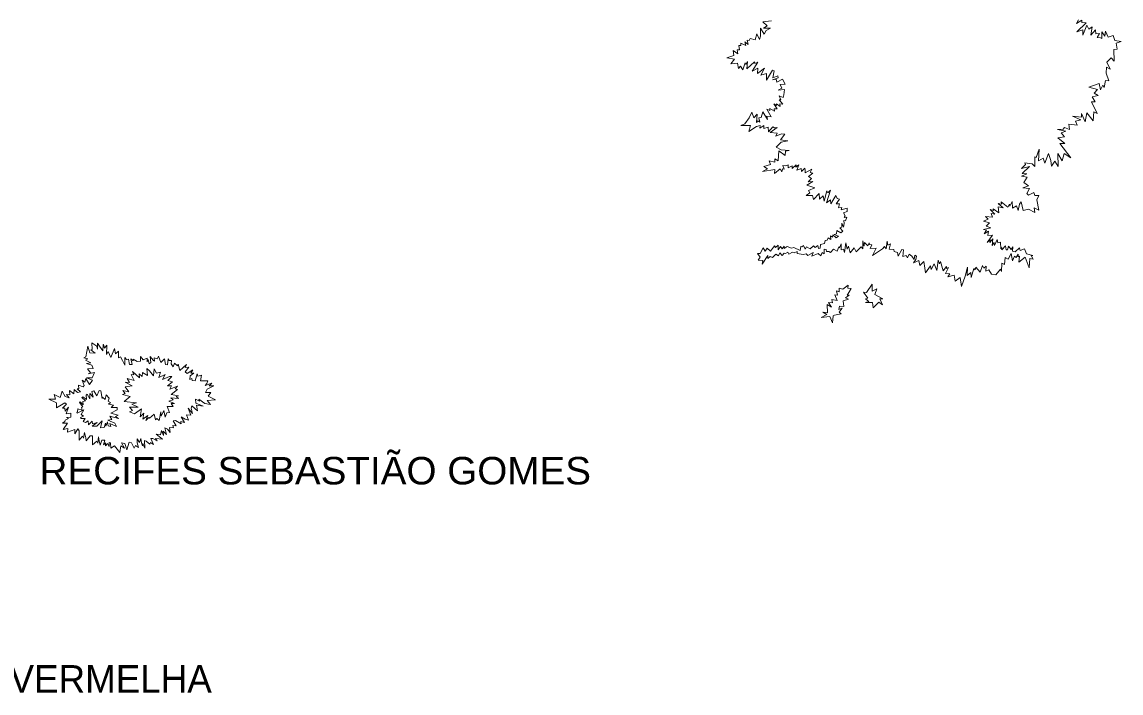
# Model space of a CAD drawing. Extents: x 47169 to 972804, y 7447977 to 9608469.
# Drawn here: x 483748 to 509726, y 8012871 to 8028731 of the extents above; entities that cross this region are included whole.
import ezdxf

# ---------------------------------------------------------------- set-up
doc = ezdxf.new("R2010")
doc.units = 0
doc.header["$LTSCALE"] = 270
doc.layers.add('1', color=7, linetype='Continuous', lineweight=13)
doc.layers.add('3', color=7, linetype='Continuous')

msp = doc.modelspace()

# ---------------------------------------------------------------- linework, layer by layer
at = {"layer": '1'}
for points in [[(500832.5, 8026326.6), (500934.2, 8026466), (501003.1, 8026598.7), (501048.6, 8026463.8), (501127, 8026550), (501106.9, 8026354.2), (501139.8, 8026397.4), (501188.5, 8026366.4), (501163.1, 8026463.8), (501219.2, 8026473.7), (501257.4, 8026605.4), (501369.7, 8026422.8), (501351.7, 8026506.9), (501455.5, 8026485.9), (501351.7, 8026669.5), (501428, 8026638.5), (501428, 8026689.4), (501539.2, 8026623), (501529.7, 8026681.7), (501598.6, 8026679.5), (501519.1, 8026796.7), (501580.6, 8026755.8), (501582.7, 8026796.7), (501671.7, 8026732.6), (501659, 8026796.7), (501733.2, 8026789), (501642, 8026887.5), (501682.3, 8026887.5), (501642, 8026984.8), (501738.5, 8026946.1), (501756.5, 8027010.2), (501771.3, 8027134.2), (501624, 8027118.7), (501709.9, 8027167.4), (501669.6, 8027255.9), (501784, 8027259.2), (501722.6, 8027375.4), (501593.3, 8027306.8), (501573.2, 8027378.7), (501489.5, 8027363.2), (501624.1, 8027414.1), (501611.4, 8027455), (501493.7, 8027408.6), (501529.8, 8027576.7), (501489.5, 8027594.4), (501344.3, 8027357.7), (501349.6, 8027510.4), (501208.7, 8027475), (501303, 8027637.6), (501130.3, 8027510.4), (501140.9, 8027637.6), (501008.4, 8027566.8), (501137.7, 8027784.8), (501072, 8027747.1), (501059.3, 8027792.5), (500881.3, 8027619.9), (500899.3, 8027800.2), (500861.2, 8027726.1), (500843.1, 8027764.9), (500789.1, 8027596.7), (500730.8, 8027688.5), (500683.1, 8027627.7), (500657.7, 8027757.1), (500507.2, 8027743.8), (500588.8, 8027851.2), (500407.6, 8027884.4), (500570.8, 8027935.2), (500560.2, 8028056.9), (500672.5, 8027980.6), (500652.4, 8028074.6), (500710.7, 8028069.1), (500692.7, 8028176.4), (500738.2, 8028176.4), (500739.3, 8028227.3), (500861.2, 8028178.6), (500837.9, 8028260.5), (500914.2, 8028199.7), (500888.7, 8028303.6), (500937.5, 8028295.9), (500962.9, 8028339), (501079.5, 8028311.4), (501117.6, 8028453), (501181.2, 8028315.8), (501201.3, 8028397.7), (501204.5, 8028582.4), (501293.5, 8028440.8), (501342.3, 8028527.1), (501438.7, 8028582.4), (501273.4, 8028582.4), (501364.5, 8028638.8), (501257.5, 8028730.7), (501464.2, 8028760.5)], [(508722, 8028784.1), (508671.1, 8028694.5), (508801.5, 8028770.8), (508803.5, 8028717.7), (508905.3, 8028712.1), (508681.6, 8028494.3), (508821.5, 8028547.3), (508821.4, 8028417.9), (508920.1, 8028654.6), (508963.5, 8028562.7), (509045.1, 8028613.6), (509012.2, 8028422.2), (509123.5, 8028545), (509131.9, 8028453.1), (509215.7, 8028455.3), (509161.6, 8028361.3), (509241, 8028353.5), (509276, 8028341.3), (509276.1, 8028496.2), (509342.8, 8028397.7), (509355.6, 8028513.9), (509424.4, 8028372.2), (509543.1, 8028412), (509576.9, 8028290.3), (509726.3, 8028272.5), (509615, 8028227.2), (509637.2, 8028086.7), (509555.6, 8028082.3), (509564, 8027807.9), (509497.2, 8027884.3), (509388.1, 8027782.6), (509471.7, 8027612.1), (509380.6, 8027663.1), (509372, 8027520.4), (509440.8, 8027340), (509357.1, 8027350), (509324.2, 8027182.9), (509293.5, 8027236), (509240.5, 8027126.6), (509206.6, 8027273.7), (508962.9, 8027193.1), (509173.7, 8027132.1), (509095.3, 8027050.3), (509184.2, 8026991.6), (509044.4, 8026961.8), (509112.1, 8026844.5), (509026.3, 8026842.3), (509160.7, 8026570.1), (509086.6, 8026605.5), (509064.2, 8026397.5), (508917, 8026580.2), (508875.6, 8026370), (508794.1, 8026564.7), (508792, 8026484), (508577.9, 8026501.8), (508773.9, 8026417.6), (508648.9, 8026384.5), (508690.2, 8026290.4), (508492, 8026315.9)], [(503123.9, 8023975.3), (503164.2, 8023881.3), (503182.2, 8023967.6), (503174.8, 8024038.4), (503209.8, 8024028.4), (503242.6, 8024114.7), (503182.2, 8024112.5), (503204.5, 8024150.1), (503169.5, 8024216.5), (503253.2, 8024255.2), (503251.1, 8024330.5), (503113.4, 8024287.3), (503126.1, 8024343.8), (503044.5, 8024338.2), (503075.3, 8024432.3), (502996.9, 8024435.6), (503070, 8024544), (503013.9, 8024555.1), (502986.3, 8024628.1), (502869.7, 8024432.3), (502857, 8024524.1), (502764.9, 8024453.3), (502857.1, 8024753.1), (502795.6, 8024696.7), (502775.5, 8024743.2), (502708.7, 8024498.7), (502686.5, 8024618.2), (502602.8, 8024544.1), (502594.3, 8024676.8), (502459.8, 8024537.5), (502434.3, 8024633.7), (502283.9, 8024633.7), (502370.8, 8024692.4), (502340, 8024747.7), (502490.5, 8024808.5), (502301.9, 8024877.1), (502439.7, 8024959), (502330.5, 8024951.2), (502406.8, 8025033.1), (502340.1, 8025078.5), (502445, 8025154.8), (502381.4, 8025176.9), (502421.7, 8025251.1), (502263.8, 8025167), (502263.8, 8025227.9), (502249, 8025276.5), (502170.6, 8025195.8), (502162.1, 8025264.4), (502065.7, 8025227.9), (502114.5, 8025352.9), (502043.5, 8025302), (502047.7, 8025355.1), (501953.4, 8025271), (501951.3, 8025333), (501854.9, 8025282.1), (501854.9, 8025355.1), (501804, 8025327.5), (501733, 8025335.2), (501765.9, 8025253.3), (501727.7, 8025261.1), (501711.8, 8025188.1), (501669.5, 8025256.7), (501533.8, 8025147.2), (501542.3, 8025246.7), (501254.1, 8025195.9), (501373.9, 8025258.9), (501282.7, 8025317.5), (501442.7, 8025365.1), (501412, 8025449.2), (501544.4, 8025421.5), (501542.3, 8025497.9), (501620.7, 8025449.2), (501640.9, 8025685.9), (501791.3, 8025574.2), (501793.4, 8025678.2), (501885.6, 8025693.7), (501691.7, 8025709.2), (501572, 8025768.9), (501689.6, 8025893.9), (501852.8, 8025924.9), (501674.8, 8025947), (501776.5, 8026082), (501704.5, 8026084.2), (501564.6, 8026034.5), (501600.7, 8026103), (501435.4, 8026115.2), (501595.4, 8026240.2), (501539.2, 8026229.2), (501493.6, 8026254.6), (501397.2, 8026135.2), (501384.5, 8026244.7), (501282.8, 8026211.5), (501284.9, 8026283.4), (501190.6, 8026222.6), (501199.1, 8026287.8), (501110.1, 8026258), (500928.9, 8026138.5), (500964.9, 8026285.6), (500748.8, 8026287.9), (500741.4, 8026287.9), (500832.5, 8026326.6)], [(508492, 8026315.9), (508512.1, 8026186.5), (508390.3, 8026239.6), (508359.5, 8026199.8), (508221.8, 8026192.1), (508419.9, 8026153.3), (508312.9, 8026113.5), (508389.1, 8026016.2), (508229.1, 8025994.1), (508401.8, 8025856.8), (508277.8, 8025861.3), (508539.4, 8025523.7), (508379.4, 8025622.3), (508338, 8025451.9), (508236.4, 8025625.7), (508243.7, 8025314.8), (508163.2, 8025437.6), (508086.9, 8025325.9), (508068.9, 8025457.6), (508010.7, 8025620.2), (507921.6, 8025391.2), (507887.8, 8025514.1), (507778.6, 8025449.9), (507794.6, 8025722.1), (507720.4, 8025531.8), (507687.5, 8025541.8), (507689.6, 8025315), (507629.2, 8025377), (507450.2, 8025402.5), (507468.1, 8025361.5), (507377, 8025269.8), (507562.4, 8025312.8), (507391.8, 8025150.2), (507498.8, 8025140.3), (507376.9, 8025083.9), (507506.2, 8025061.7), (507427.7, 8024934.5), (507538.9, 8024860.3), (507407.5, 8024812.8), (507562.2, 8024791.7), (507500.7, 8024675.6), (507538.9, 8024639.1), (507661.8, 8024701), (507691.4, 8024626.8), (507780.4, 8024626.8), (507732.7, 8024525), (507783.5, 8024281.6), (507671.2, 8024337), (507687, 8024225.2), (507541.9, 8024309.4), (507409.5, 8024274), (507366.1, 8024482), (507327.9, 8024423.4), (507297.2, 8024274.1), (507257, 8024385.8), (507164.8, 8024332.7), (507155.3, 8024489.9), (507097, 8024375.9), (507091.7, 8024426.8), (507050.3, 8024352.7), (506890.4, 8024476.7), (506897.8, 8024421.4), (506821.5, 8024441.3), (506939.1, 8024335), (506821.5, 8024360.5), (506841.6, 8024223.3), (506701.8, 8024311.9), (506714.5, 8024276.5), (506630.8, 8024299.7), (506739.9, 8024190.2), (506659.4, 8024205.7), (506686.9, 8024113.9), (506526.9, 8024133.8), (506587.3, 8024072.9), (506478.1, 8024025.4), (506615.8, 8023982.2), (506536.4, 8023905.9), (506646.5, 8023867.1), (506478.1, 8023824), (506544.8, 8023811.9), (506490.7, 8023722.3), (506595.6, 8023783.1), (506577.6, 8023686.8), (506692, 8023692.3), (506564.8, 8023516.5), (506635.8, 8023592.8), (506625.2, 8023519.8), (506697.3, 8023602.7), (506681.3, 8023445.6), (506730.1, 8023521.9), (506737.5, 8023451.1), (506795.8, 8023590.5), (506811.7, 8023511.9), (506879.5, 8023526.3), (506887.9, 8023367), (506908, 8023400.2), (506908, 8023346), (506997, 8023443.3), (507009.7, 8023349.2), (507040.4, 8023345.9), (507065.9, 8023435.5)], [(503652.5, 8023442), (503647.2, 8023436.4), (503627.1, 8023558.1), (503623.9, 8023370.1), (503583.6, 8023416.5), (503463.9, 8023297.1), (503416.2, 8023395.5), (503326.2, 8023276.1), (503286, 8023431), (503253.1, 8023362.4), (503224.5, 8023507.3), (503186.3, 8023283.8), (503166.2, 8023360.2), (503110.1, 8023348), (503110.1, 8023485.2), (503069.8, 8023391.2), (503055, 8023416.6), (503016.8, 8023311.5), (502930, 8023362.4), (502859, 8023283.9), (502820.9, 8023304.9), (502762.6, 8023304.9), (502759.4, 8023350.3), (502711.7, 8023358), (502711.7, 8023254), (502659.8, 8023283.9), (502634.4, 8023203.2), (502566.6, 8023261.8), (502418.3, 8023195.4), (502452.2, 8023281.7), (502321.9, 8023215.4), (502283.7, 8023250.8), (502214.9, 8023238.6), (502072.9, 8023256.3), (502072.9, 8023305), (502001.9, 8023276.2), (501960.6, 8023291.7), (501876.9, 8023243.1), (501849.4, 8023287.3), (501793.2, 8023261.9), (501762.5, 8023266.3), (501717, 8023211), (501660.8, 8023276.3), (501633.2, 8023207.7), (501566.5, 8023246.4), (501490.2, 8023162.3), (501429.9, 8023190), (501381.1, 8023144.6), (501379, 8023211), (501241.3, 8023007.5), (501261.4, 8023093.8), (501152.3, 8023101.5), (501197.8, 8023175.6), (501136.4, 8023256.4), (501200, 8023256.4), (501266.7, 8023393.6), (501312.3, 8023312.8), (501361, 8023385.8), (501442.6, 8023317.2), (501531.6, 8023442.2), (501557, 8023399.1), (501622.7, 8023454.4), (501622.7, 8023342.7), (501678.8, 8023421.2), (501713.8, 8023370.3), (501760.4, 8023434.5), (501762.5, 8023378.1), (501838.8, 8023426.7), (501938.4, 8023385.8), (501991.4, 8023403.5), (502141.8, 8023332.7), (502159.8, 8023421.2), (502185.2, 8023413.4), (502223.4, 8023444.4), (502263.6, 8023358.1), (502291.2, 8023416.7), (502375.9, 8023370.2), (502459.6, 8023436.6), (502499.9, 8023399), (502556, 8023446.6), (502574, 8023375.8), (502614.3, 8023385.7), (502622.8, 8023474.2), (502713.9, 8023493), (502731.9, 8023566), (502782.8, 8023573.8), (502800.8, 8023632.4), (502864.3, 8023587), (502861.2, 8023673.3), (502902.5, 8023642.3), (502912, 8023701), (502995.7, 8023626.8), (503044.4, 8023667.8), (502942.7, 8023708.7), (503004.2, 8023724.2), (503008.4, 8023802.8), (503105.9, 8023746.3), (503153.6, 8023787.2), (503082.6, 8023865.8), (503123.9, 8023881.3), (503123.9, 8023975.3)], [(507065.9, 8023435.5), (507126.3, 8023356.9), (507169.7, 8023420), (507164.4, 8023316), (507220.5, 8023300.5), (507329.7, 8023396.7), (507340.2, 8023331.4), (507442, 8023371.2), (507494.9, 8023251.7), (507640, 8023214), (507599.8, 8023214), (507652.7, 8023122.2), (507571.1, 8023143.2), (507558.3, 8022918.7), (507462, 8023170.9), (507309.4, 8023055.9), (507329.6, 8023193.1), (507291.5, 8023183.2), (507291.5, 8023241.8), (507248, 8023161.1), (507209.9, 8023198.7), (507162.2, 8023089.2), (507129.4, 8023262.9), (507060.5, 8023122.4), (506991.6, 8023161.2), (506968.3, 8023000.7), (506910, 8023031.7), (506899.4, 8022832.6), (506874, 8022886.8), (506764.8, 8022756.3), (506663.1, 8022767.4), (506604.9, 8022873.6), (506528.6, 8022840.5), (506539.2, 8022960), (506479.9, 8022912.4), (506450.2, 8022975.5), (506398.3, 8022820.6), (506294.5, 8022934.6), (506279.7, 8022869.3), (506248.9, 8022901.4), (506187.4, 8022691.2), (506180, 8022812.9), (506085.7, 8022742.1), (506098.5, 8022934.7), (506045.5, 8022721.1), (505956.4, 8022475.5), (505927.9, 8022695.7), (505806, 8022601.7), (505778.5, 8022746.7), (505635.5, 8022709.1), (505679, 8022779.9), (505579.4, 8022785.4), (505646.2, 8022927), (505604.8, 8022907.1), (505597.4, 8022952.5), (505524.3, 8022851.8), (505462.9, 8023067.6), (505437.5, 8023011.2), (505404.7, 8023100.8), (505404.7, 8023095.3), (505371.8, 8022856.3), (505308.2, 8023014.5), (505239.3, 8022877.4), (505226.7, 8022963.7), (505104.8, 8022805.5), (505088.9, 8022912.8), (505068.8, 8023069.9), (504967.1, 8022971.5), (504949.1, 8023095.4), (504822, 8023036.8), (504872.9, 8023115.3), (504893, 8023197.2), (504854.9, 8023220.4), (504834.7, 8023115.3), (504781.8, 8023197.2), (504722.5, 8023245.9), (504682.2, 8023156.3), (504646.2, 8023215), (504565.7, 8023189.5), (504585.8, 8023342.2), (504544.5, 8023350), (504458.7, 8023197.3), (504442.8, 8023285.8), (504364.4, 8023303.5), (504353.8, 8023350), (504242.6, 8023357.8), (504280.7, 8023485), (504217.2, 8023456.2), (504197.1, 8023553.6), (504175.8, 8023365.5), (504135.6, 8023426.4), (504086.8, 8023367.8), (503850.6, 8023212.9), (503939.6, 8023385.5), (503794.5, 8023380), (503832.6, 8023464.1), (503781.8, 8023471.8), (503772.2, 8023507.2), (503743.6, 8023436.4), (503662, 8023522.7), (503652.5, 8023442)], [(484709.3, 8019248.8), (484760.1, 8019285.3), (484765.4, 8019317.4), (484843.8, 8019356.2), (484803.5, 8019383.8), (484899.9, 8019391.6), (484899.8, 8019487.9), (484790.7, 8019467.9), (484843.5, 8019628.4), (484765.2, 8019536.5), (484762, 8019605.1), (484703.8, 8019605), (484800.1, 8019701.4), (484761.9, 8019732.3), (484567.1, 8019610.5), (484567, 8019732.2), (484383.7, 8019816.1), (484538.4, 8019818.4), (484510.7, 8019924.6), (484652.7, 8019856.1), (484693.9, 8020004.4), (484772.4, 8019879.5), (484861.4, 8019844.1), (484801, 8019928.2), (484877.2, 8019920.5), (484868.7, 8020022.2), (484970.4, 8019946), (484980.9, 8020047.8), (485062.5, 8019975.9), (485131.4, 8019989.3), (485049.8, 8020060), (485093.2, 8020057.8), (485084.7, 8020146.3), (485194.8, 8020105.5), (485215, 8020142), (485169.3, 8020268.1), (485232.9, 8020215), (485258.3, 8020301.4), (485342, 8020164.2), (485412.9, 8020261.6), (485273.1, 8020322.4), (485407.6, 8020319.2), (485458.3, 8020449.8), (485314.3, 8020418.7), (485377.9, 8020430.9), (485298.3, 8020530.4), (485432.9, 8020538.2), (485400, 8020619), (485272.8, 8020662), (485377.7, 8020675.4), (485247.3, 8020736.2), (485301.3, 8020767.2), (485212.3, 8020792.5), (485257.9, 8020814.7), (485301.1, 8021069.2), (485354.2, 8020912.2), (485479.2, 8020906.7), (485372.2, 8020985.2), (485410.3, 8020987.4), (485402.7, 8021150), (485519.3, 8021071.6), (485530, 8021000.8), (485532, 8021140.2), (485577.6, 8021067.2), (485659.2, 8020957.7), (485666.5, 8021107.1), (485671.8, 8021107.1), (485700.5, 8021018.6), (485753.4, 8021089.5), (485743, 8020868.2), (485781.1, 8020942.3), (485847.9, 8020797.4), (485931.4, 8021016.6), (485959, 8020891.6), (486031, 8020948), (486031.2, 8020789.8), (486073.5, 8020818.6), (486120.2, 8020729), (486175.3, 8020617.3), (486178.4, 8020799.9), (486221.9, 8020756.8), (486262.1, 8020762.3), (486289.7, 8020637.3), (486354.3, 8020637.4), (486323.5, 8020772.3), (486374.4, 8020721.5), (486374.4, 8020760.2), (486468.7, 8020706), (486552.4, 8020711.6), (486552.3, 8020821.2), (486612.7, 8020747.1), (486704.9, 8020782.5), (486704.9, 8020701.8), (486730.3, 8020757.1), (486752.6, 8020653.1), (486790.7, 8020686.4), (486775.8, 8020821.3), (486852.1, 8020737.3), (486879.7, 8020717.4), (486872.2, 8020793.7), (486941.1, 8020768.3)], [(486941.1, 8020768.3), (486973.9, 8020833.6), (487033.3, 8020681), (487119, 8020770.7), (487142.4, 8020637.9), (487185.9, 8020630.2), (487205.9, 8020772.9), (487223.9, 8020727.6), (487284.3, 8020729.8), (487274.8, 8020651.3), (487320.4, 8020582.7), (487351.1, 8020663.5), (487422.1, 8020600.5), (487442.2, 8020641.4), (487482.5, 8020493.2), (487635, 8020638.2), (487607.5, 8020561.9), (487691.2, 8020573), (487602.2, 8020461.2), (487653.1, 8020422.5), (487783.4, 8020508.9), (487742.1, 8020430.3), (487813.1, 8020430.3), (487722, 8020367.2), (487714.6, 8020279.8), (487765.5, 8020303.1), (487767.6, 8020259.9), (487843.9, 8020247.8), (487885.1, 8020412.7), (487905.3, 8020359.6), (487994.2, 8020387.3), (487966.8, 8020250.1), (488144.7, 8020252.4), (488114, 8020186), (488075.9, 8020140.6), (488233.7, 8020193.8), (488174.5, 8020132.9), (488281.4, 8020128.6), (488126.8, 8020052.2), (488083.5, 8019973.6), (488212.7, 8019972.5), (488152.4, 8019889.5), (488322.9, 8019800)], [(488322.9, 8019800), (488123.8, 8019782.2), (488203.3, 8019691.5), (488067.7, 8019713.6), (487927.8, 8019817.5), (487945.9, 8019772.1), (487847.3, 8019817.4), (487854.8, 8019723.4), (488032.8, 8019652.7), (487872.9, 8019672.5), (487900.5, 8019540.9), (487762.7, 8019658), (487747.9, 8019601.6), (487775.5, 8019477.7), (487673.8, 8019601.6), (487735.3, 8019441.2), (487635.7, 8019448.9), (487686.7, 8019317.2), (487608.2, 8019347.1), (487514, 8019395.7), (487592.4, 8019266.3), (487501.3, 8019291.7), (487514, 8019233), (487374.2, 8019309.3), (487323.4, 8019301.5), (487392.3, 8019189.8), (487312.8, 8019192), (487330.9, 8019141.1), (487231.3, 8019148.8), (487252.6, 8019029.3), (487183.7, 8019105.6), (487127.5, 8019141), (487163.6, 8018981.7), (487087.3, 8019058), (487091.6, 8018958.4), (487046, 8019072.3), (487020.7, 8018976.1), (486922.1, 8018989.3), (487071.5, 8018869.9), (486906.3, 8018887.5), (486942.4, 8018828.9), (486842.8, 8018887.4), (486795.1, 8018887.4), (486855.6, 8018742.5), (486784.6, 8018793.3), (486766.6, 8018752.4), (486685, 8018820.9), (486646.9, 8018838.6), (486650.2, 8018658.3), (486603.5, 8018767.8), (486596.1, 8018711.3), (486573.8, 8018785.5), (486561, 8018887.2), (486525.1, 8018795.4), (486466.8, 8018879.4), (486474.2, 8018783.2), (486499.7, 8018671.5), (486430.9, 8018719), (486403.4, 8018658.1), (486339.7, 8018787.5), (486281.5, 8018797.4), (486225.5, 8018622.6), (486179.8, 8018769.7), (486102.5, 8018782.9), (486174.6, 8018660.2), (486082.4, 8018711), (486064.5, 8018556.1), (485935.2, 8018710.9), (485851.5, 8018659.9), (485840.9, 8018787.2), (485810.2, 8018792.7), (485806, 8018698.6), (485772, 8018765), (485721.2, 8018716.3), (485721.2, 8018784.9), (485675.7, 8018733.9), (485704.2, 8018851.2), (485635.3, 8018851.2), (485592, 8018728.3), (485573.9, 8018827.9), (485559, 8018927.5), (485543.2, 8018774.8), (485513.6, 8018825.7), (485414.1, 8018733.7), (485413.9, 8018952.8), (485363.1, 8018952.8), (485263.6, 8018827.7), (485254, 8018901.8), (485225.3, 8019031.2), (485205.3, 8018894), (485179.8, 8018941.6), (485101.5, 8018845.2), (485101.4, 8019064.3), (485067.4, 8019115.2), (484999.7, 8018997.9), (484999.7, 8019101.9), (484821.8, 8019035.3), (484831.2, 8019125), (484722.2, 8019101.6), (484823.7, 8019246.7), (484709.3, 8019248.8)]]:
    msp.add_lwpolyline(points, dxfattribs=at)
for points in [[(502921.3, 8021782.5), (502908.5, 8021624.3), (502842.9, 8021769.3), (502639.5, 8021743.9), (502768.7, 8021815.8), (502679.8, 8021871.1), (502792, 8021853.4), (502779.4, 8022056.9), (502878.9, 8021990.5), (502815.4, 8022097.9), (502909.7, 8022094.5), (502888.5, 8022173.1), (503013.5, 8022151), (502964.8, 8022280.4), (503024.1, 8022278.2), (503002.9, 8022374.4), (503062.2, 8022353.4), (503064.4, 8022443), (503151.2, 8022417.5), (503273.1, 8022511.6), (503271, 8022437.5), (503349.3, 8022433), (503295.3, 8022341.2), (503249.7, 8022270.4), (503300.6, 8022274.8), (503214.8, 8022211.8), (503282.5, 8022180.8), (503160.7, 8022141), (503176.6, 8022006), (503074.9, 8022013.7), (503059, 8021937.4), (503133.2, 8021965.1), (503062.2, 8021873.2), (503113, 8021835.6), (502952, 8021804.7)], [(503845.1, 8022534.7), (503845.1, 8022372.1), (503952.1, 8022427.4), (503903.4, 8022290.2), (504099.3, 8022186.2), (504025.2, 8022186.2), (504091.9, 8022045.7), (504005, 8022107.6), (503865.2, 8021974.9), (503855.6, 8022099.9), (503685.1, 8022104.4), (503761.4, 8022125.4), (503690.4, 8022184), (503745.5, 8022201.7), (503636.4, 8022343.4), (503710.6, 8022333.4)], [(486234.9, 8020302.1), (486402.3, 8020259), (486328, 8020401.7), (486394.8, 8020388.5), (486364, 8020470.3), (486524, 8020323.3), (486516.6, 8020411.8), (486590.7, 8020351), (486592.8, 8020442.8), (486712.5, 8020374.3), (486699.7, 8020541.4), (486763.3, 8020486.1), (486854.5, 8020371.1), (486870.3, 8020529.3), (486930.7, 8020427.5), (487019.7, 8020453), (486981.6, 8020328), (487134.1, 8020402.2), (487066.4, 8020282.7), (487231.6, 8020349.2), (487292, 8020351.5), (487193.5, 8020259.5), (487302.6, 8020224.2), (487185.1, 8020132.3), (487282.6, 8020130.2), (487246.6, 8020051.6), (487427.7, 8020120.3), (487366.3, 8020059.4), (487424.6, 8020044), (487277.4, 8019926.6), (487448, 8019891.3), (487391.8, 8019875.8), (487448, 8019832.7), (487264.8, 8019850.2), (487323, 8019799.4), (487216.1, 8019771.7), (487355.9, 8019716.4), (487274.4, 8019710.9), (487323.1, 8019642.3), (487183.3, 8019642.2), (487234.3, 8019497.3), (487172.8, 8019497.2), (487134.8, 8019387.7), (487101.8, 8019548.1), (487040.5, 8019410.9), (487033, 8019517.1), (486989.7, 8019311.3), (486938.8, 8019357.7), (486906, 8019328.9), (486873.1, 8019461.7), (486764.1, 8019369.8), (486746, 8019383), (486677.2, 8019311), (486725.9, 8019428.4), (486604.1, 8019342), (486631.6, 8019489.1), (486542.7, 8019400.6), (486573.2, 8019585.4), (486404.9, 8019471.3), (486290.5, 8019516.6), (486362.5, 8019547.6), (486290.4, 8019629.4), (486491.7, 8019629.6), (486344.4, 8019694.7), (486451.4, 8019725.8), (486166.4, 8019761), (486306.1, 8019880.6), (486122.9, 8019925.8), (486186.4, 8019949.1), (486130.2, 8020017.6), (486270, 8019990.1), (486188.4, 8020106.2), (486353.6, 8020129.5), (486184.1, 8020217.9), (486285.8, 8020208)], [(486029, 8019357.1), (485825.6, 8019417.8), (485869.1, 8019335.9), (485774.8, 8019321.5), (485945.4, 8019249.7), (485985.7, 8019171.2), (485822.5, 8019237.4), (485851.2, 8019166.7), (485784.4, 8019188.7), (485769.5, 8019278.3), (485733.6, 8019176.5), (485724, 8019252.9), (485691.3, 8019147.7), (485602.3, 8019141), (485640.3, 8019308.1), (485517.5, 8019178.6), (485403.1, 8019178.5), (485528.1, 8019262.7), (485413.7, 8019234.9), (485406.2, 8019300.2), (485319.5, 8019206.1), (485312, 8019307.9), (485246.3, 8019264.7), (485190.2, 8019287.9), (485237.8, 8019358.7), (485144.6, 8019358.6), (485131.8, 8019384.1), (485199.6, 8019411.8), (485148.7, 8019450.5), (485208, 8019562.3), (485052.3, 8019488), (485047, 8019505.7), (485062.9, 8019516.8), (485065, 8019589.8), (485174.1, 8019560), (485151.8, 8019620.9), (485189.9, 8019638.6), (485108.3, 8019740.3), (485121, 8019750.3), (485197.3, 8019679.5), (485189.8, 8019760.3), (485245.9, 8019775.8), (485164.3, 8019856.5), (485184.4, 8019869.8), (485273.5, 8019805.7), (485262.8, 8019910.8), (485288.2, 8019930.7), (485351.8, 8019826.8), (485351.7, 8019946.3), (485431.2, 8019864.5), (485395.1, 8019997.2), (485449.1, 8020009.4), (485518.1, 8019897.7), (485570.9, 8020019.5), (485611.2, 8020009.5), (485639.9, 8019829.2), (485654.7, 8019860.2), (485713, 8019806), (485734.1, 8019915.6), (485805.2, 8019837.1), (485781.9, 8019766.2), (485838.1, 8019740.9), (485789.4, 8019694.3), (485914.4, 8019676.7), (485853, 8019621.4), (485996, 8019621.5), (485996, 8019562.8), (485851, 8019488.6), (486023.6, 8019437.8), (485960.1, 8019404.6)]]:
    msp.add_lwpolyline(points, close=True, dxfattribs=at)

# ---------------------------------------------------------------- texts
at = {"layer": '3', "width": 1.05}
msp.add_text('RECIFES SEBASTIÃO GOMES', height=650.1, dxfattribs=at).set_placement((484162.4, 8017801.3))
at = {"layer": '3'}
msp.add_text('COROA VERMELHA', height=649.9, dxfattribs=at).set_placement((480024.8, 8012880.6))

doc.saveas('drawing.dxf')
